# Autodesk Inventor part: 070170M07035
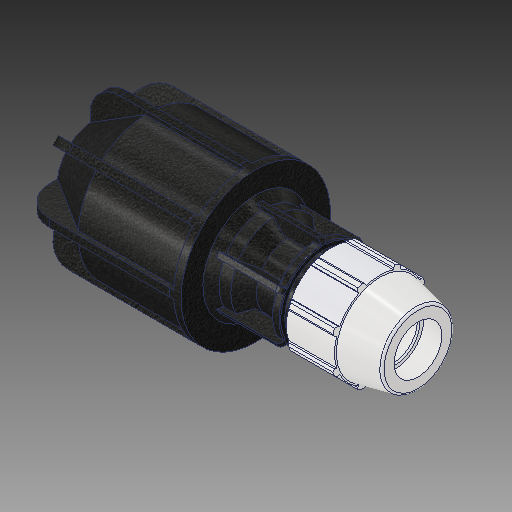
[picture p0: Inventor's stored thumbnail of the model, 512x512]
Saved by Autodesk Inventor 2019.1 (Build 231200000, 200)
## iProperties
Created: 2017-02
Part Number: 070170M07035
Material: PVC-Piping
Description: PLASSON PLASS4 COUPLING 3/4'' - 1.22
Document SubType Name: Modeling
Designer: KIM
Mass: 92.6774 g
Surface Area: 199.44 cm^2
Volume: 66.1981 cm^3
Density: 1.4 g/cm^3
Appearance: PTFE
Author: KIM
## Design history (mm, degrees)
derived "070170M0.ipt"
feature "Solid1::070170M0.ipt"
tag "TaggingFeature1"
body "Solid1"
other parameters: "d2" = 26.6, "d4" = 12.86329, "d5" = 20.9804, "d7" = 54.102, "d8" = 35.68618, "d9" = 11.57143, "d11" = 4.50215, "d12" = 43.2816, "d13" = 120 deg, "d14" = 39.9, "d15" = 12 deg, "d16" = 48.6918, "d18" = 1.33, "d19" = 35 deg, "d20" = 17.5 deg, "d21" = 50.31486, "d23" = 0, "d25" = 360 deg, "d27" = 1.08204, "d42" = 26.9748, "d43" = 1.62306, "d46" = 0.798, "d53" = 0.532, "d67" = 2.7051, "d70" = 23.94, "d71" = 59.944, "d74" = 180 deg, "d75" = 30.988, "d76" = 83.058, "d80" = 23.94, "d84" = 78.9051, "d85" = 135 deg, "d86" = 4.1529, "d89" = 4.1529, "d90" = 135 deg, "d94" = 4.1529, "d97" = 4.32816, "d98" = 0, "d100" = 360 deg, "d102" = 91.3638, "d103" = 16.6116, "d104" = 6.64464, "d105" = 0, "d110" = 89.916, "d112" = 108.0516, "d113" = 30.57144, "d114" = 72.0344, "d115" = 49.8348, "d116" = 108.0516, "d117" = 4.4958, "d118" = 27.051, "d119" = 2.7051, "d120" = 0, "d121" = 2.7051, "d123" = 360 deg, "d_" = 26.6, "E_" = 54.102, "A_" = 81, "l_" = 59.944, "d_1" = 30.988, "E_1" = 83.058, "l_1" = 89.916, "H_" = 180.086, "d106" = 35.68618
